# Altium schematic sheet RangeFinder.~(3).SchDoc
size A
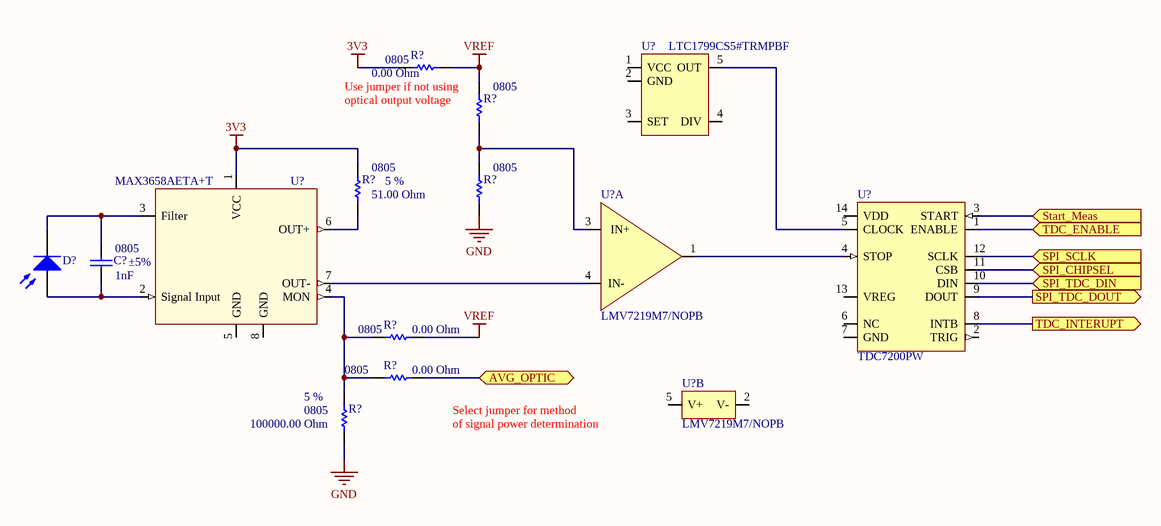
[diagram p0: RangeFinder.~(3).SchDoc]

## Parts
(Parts that share a designator on the sheet are numbered #1, #2 ... from top to bottom, then left to right.)
C?  value 1nF  Tolerance: ±5%  Case-EIA: 0805  [CAPC0805(2012)100_M]  (hidden comment: CAP 1nF 6.3V 0805(2012))
D?  Photo Sen  [PIN2]  (value not drawn)
R?#1  value 0.00 Ohm  Case-EIA: 0805  [RESC0805(2012)_N]  (hidden comment: Jumper 0805(2012))
R?#2  Case-EIA: 0805  [RESC0805(2012)_N]  (hidden comment: 51R 5% 0805(2012))
R?#3  value 51.00 Ohm  Tolerance: 5 %  Case-EIA: 0805  [RESC0805(2012)_N]  (hidden comment: 51R 5% 0805(2012))
R?#4  Case-EIA: 0805  [RESC0805(2012)_N]  (hidden comment: 51R 5% 0805(2012))
R?#5  value 0.00 Ohm  Case-EIA: 0805  [RESC0805(2012)_N]  (hidden comment: Jumper 0805(2012))
R?#6  value 0.00 Ohm  Case-EIA: 0805  [RESC0805(2012)_N]  (hidden comment: Jumper 0805(2012))
R?#7  value 100000.00 Ohm  Tolerance: 5 %  Case-EIA: 0805  [RESC0805(2012)_L]  (hidden comment: 100K 5% 0805(2012))
U?#1  LTC1799CS5#TRMPBF
U?#2  MAX3658AETA+T
U?#3  LMV7219M7/NOPB  (part A of 2)
U?#4  TDC7200PW
U?#5  LMV7219M7/NOPB  (part B of 2)

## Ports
AVG_OPTIC, SPI_CHIPSEL (in), SPI_SCLK (in), SPI_TDC_DIN (in), SPI_TDC_DOUT (out), Start_Meas (in), TDC_ENABLE (in), TDC_INTERUPT (out)

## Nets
3V3: R?#1.1 R?#3.2 U?#2.1(VCC)
GND: R?#4.1 R?#7.1 U?#2.9(PAD)
VREF: R?#1.2 R?#2.2 R?#5.2
AVG_OPTIC: R?#6.2 ; port AVG_OPTIC
SPI_CHIPSEL: U?#4.11(CSB) ; port SPI_CHIPSEL
SPI_SCLK: U?#4.12(SCLK) ; port SPI_SCLK
SPI_TDC_DIN: U?#4.10(DIN) ; port SPI_TDC_DIN
SPI_TDC_DOUT: U?#4.9(DOUT) ; port SPI_TDC_DOUT
Start_Meas: U?#4.3(START) ; port Start_Meas
TDC_ENABLE: U?#4.1(ENABLE) ; port TDC_ENABLE
TDC_INTERUPT: U?#4.8(INTB) ; port TDC_INTERUPT
NetC?_1: C?.1 D?.1(A) U?#2.2(Signal_Input)
NetC?_2: C?.2 D?.2(K) U?#2.3(Filter)
NetR?#2_1: R?#2.1 R?#4.2 U?#3.3(IN+)
NetR?#3_1: R?#3.1 U?#2.6(OUT+)
NetR?#5_1: R?#5.1 R?#6.1 R?#7.2 U?#2.4(MON)
NetU?#1_5: U?#1.5(OUT) U?#4.5(CLOCK)
NetU?#2_7: U?#2.7(OUT-) U?#3.4(IN-)
NetU?#3_1: U?#3.1(OUT) U?#4.4(STOP)

Not connected (* = marked no-connect by the designer): U?#1 1(VCC) 2(GND) 3(SET) 4(DIV); U?#2 5(GND) 8(GND); U?#4 2(TRIG) 6(NC) 7(GND) 13(VREG) 14(VDD); U?#5 2(V-) 5(V+)

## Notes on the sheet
- (near R?#2) Use jumper if not using
- (near R?#2) optical output voltage
- (near R?#6) Select jumper for method
- of signal power determination

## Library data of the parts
C? = CMP-1036-02947-1: CAP 1nF 6.3V ±5% 0805 (2012 Metric) Thickness 1mm SMD; Case-Metric: 2012
D? = Photo Sen: Photosensitive Diode
R?#1 R?#5 R?#6 = CMP-1013-00001-1: Jumper 0805 (2012 Metric); Tolerance: None; Case-Metric: 2012
R?#2 R?#4 = CMP-1013-00043-1: 51R 0.125W 5% 0805 (2012 Metric)  SMD; Value: 51.00 Ohm; Case-Metric: 2012
R?#3 = CMP-1013-00043-1: 51R 0.125W 5% 0805 (2012 Metric)  SMD; Case-Metric: 2012
R?#7 = CMP-1013-00122-1: 100K 0.125W 5% 0805 (2012 Metric)  SMD; Case-Metric: 2012
U?#1 = LTC1799CS5#TRMPBF: IC OSC SILICON PROG TSOT23-5
U?#2 = MAX3658AETA+T: IC AMP TRANSIMPEDANCE 8-TDFN
U?#3 U?#5 = LMV7219M7/NOPB: IC COMPARATOR SC-70-5
U?#4 = TDC7200PW: STATIC ULTRASONIC FLOWMETER AF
